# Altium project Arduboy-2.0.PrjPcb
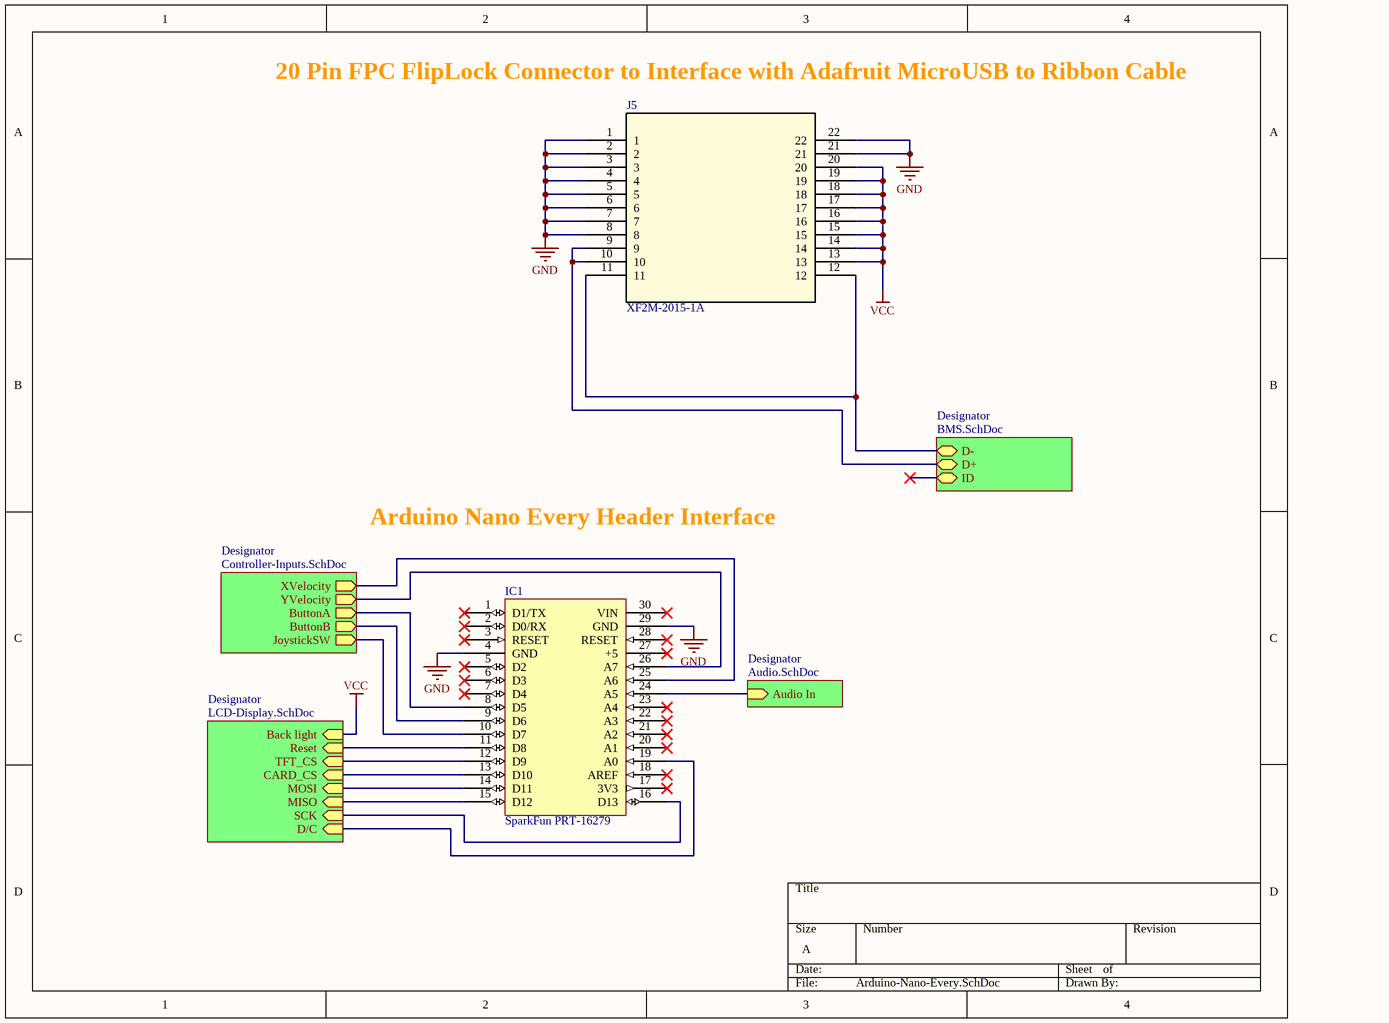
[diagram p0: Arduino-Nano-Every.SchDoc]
5 sheets, 40 parts. Net scope: hierarchical (ports join the sheet entries above them; power ports are global).
Sheets:
  Arduino-Nano-Every.SchDoc
    Designator = BMS.SchDoc
    Designator = Controller-Inputs.SchDoc
    Designator = LCD-Display.SchDoc
    Designator = Audio.SchDoc

## Sheet Arduino-Nano-Every.SchDoc
size A; SheetNumber: 1; SheetTotal: 5

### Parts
IC1  SparkFun PRT-16279  [PCB-djo2kohhk2l0t1bx5udn-1]
J5  XF2M-2015-1A  [CON20_1X20_DRB_XF2C_TYC]

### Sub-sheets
Designator = BMS.SchDoc: ID (bidir), D- (bidir), D+ (bidir)
Designator = Controller-Inputs.SchDoc: XVelocity (out), ButtonA (out), YVelocity (out), JoystickSW (out), ButtonB (out)
Designator = LCD-Display.SchDoc: Back light (in), CARD_CS (in), D/C (in), MISO (in), MOSI (in), SCK (in), TFT_CS (in), Reset (in)
Designator = Audio.SchDoc: Audio In (in)

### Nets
GND: IC1.4(GND) IC1.29(GND) J5.1 J5.2 J5.3 J5.4 J5.5 J5.6 J5.7 J5.8 J5.21 J5.22
VCC: J5.13 J5.14 J5.15 J5.16 J5.17 J5.18 J5.19 J5.20 ; sheet Designator/Back light
NetC8_2: IC1.24(A5) ; sheet Designator/Audio In
NetIC1_8: IC1.8(D5) ; sheet Designator/ButtonA
NetIC1_9: IC1.9(D6) ; sheet Designator/ButtonB
NetIC1_10: IC1.10(D7) ; sheet Designator/JoystickSW
NetIC1_11: IC1.11(D8) ; sheet Designator/Reset
NetIC1_12: IC1.12(D9) ; sheet Designator/TFT_CS
NetIC1_13: IC1.13(D10) ; sheet Designator/CARD_CS
NetIC1_14: IC1.14(D11) ; sheet Designator/MOSI
NetIC1_15: IC1.15(D12) ; sheet Designator/MISO
NetIC1_16: IC1.16(D13) ; sheet Designator/SCK
NetIC1_19: IC1.19(A0) ; sheet Designator/D/C
NetIC1_25: IC1.25(A6) ; sheet Designator/XVelocity
NetIC1_26: IC1.26(A7) ; sheet Designator/YVelocity
NetJ3_2: J5.11 J5.12 ; sheet Designator/D-
NetJ3_3: J5.9 J5.10 ; sheet Designator/D+

Not connected (* = marked no-connect by the designer): IC1 1(D1/TX)* 2(D0/RX)* 3(RESET)* 5(D2)* 6(D3)* 7(D4)* 17(3V3)* 18(AREF)* 20(A1)* 21(A2)* 22(A3)* 23(A4)* 27(+5)* 28(RESET)* 30(VIN)*

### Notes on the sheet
- 20 Pin FPC FlipLock Connector to Interface with Adafruit MicroUSB to Ribbon Cable
- Arduino Nano Every Header Interface

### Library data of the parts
IC1 = CMP-cc85030fd7841342-2: Arduino Nano Stackable Headers
J5 = XF2M-2015-1A: No Description Available; Mfr_Name: Omron

## Sheet BMS.SchDoc
size A; SheetNumber: 4; SheetTotal: 5
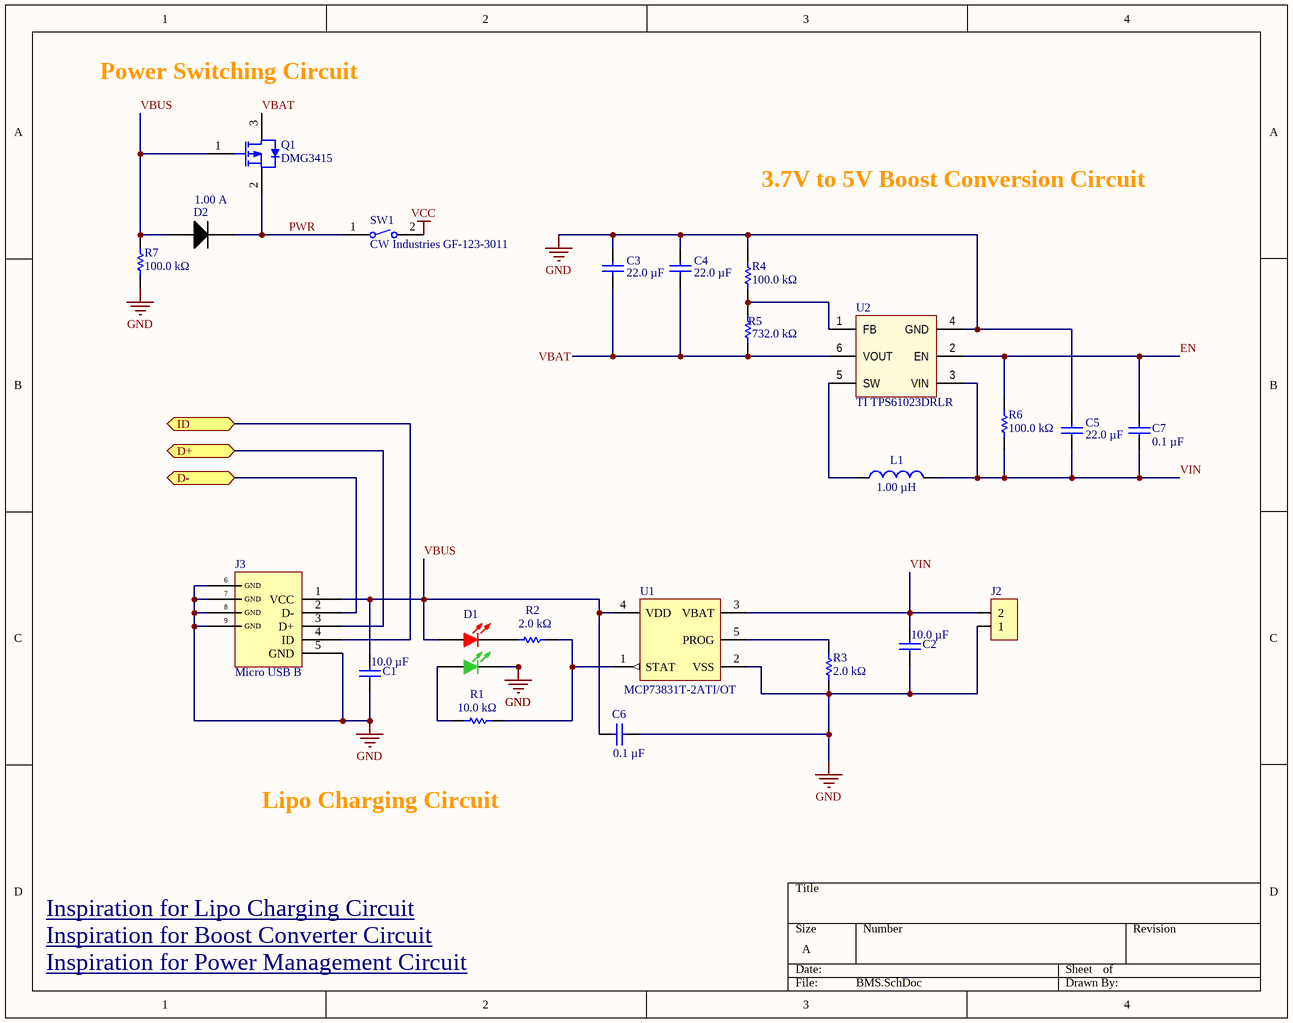
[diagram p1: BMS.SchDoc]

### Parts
C1  Capacitance: 10.0 µF  [CAPC2013X140X50LL20T25]  (hidden comment: Yageo CC0805ZKY5V6BB106)
C2  Capacitance: 10.0 µF  [CAPC2013X140X50LL20T25]  (hidden comment: Yageo CC0805ZKY5V6BB106)
C3  Capacitance: 22.0 µF  [0805_A]  (hidden comment: Murata GRM21BR60J226ME39L)
C4  Capacitance: 22.0 µF  [0805_A]  (hidden comment: Murata GRM21BR60J226ME39L)
C5  Capacitance: 22.0 µF  [0805_A]  (hidden comment: Murata GRM21BR60J226ME39L)
C6  Capacitance: 0.1 µF  [PCB-nrkqodghfh3vhkjrqn6s-1]  (hidden comment: Capacitor 0.1 uF 50V 0805 smd)
C7  Capacitance: 0.1 µF  [PCB-nrkqodghfh3vhkjrqn6s-1]  (hidden comment: Capacitor 0.1 uF 50V 0805 smd)
D1  Kingbright APHBM2012SURKCGKC  [PCB-7tltpeahe5b5uing7o0a-1]  (value not drawn)
D2  Current Rating: 1.00 A  [PCB-ug07xgv2o38opsue5tpb-1]  (hidden comment: ON Semiconductor MBR120VLSFT1G)
J2  JST S2B-PH-SM4-TB(LF)(SN)  [PCB-h6x3au1s0qq8morn82dx-1]  (value not drawn)
J3  Micro USB B  [PCB-c9crxyc84g0j6lvlvhpi-1]
L1  Inductance: 1.00 µH  [PCB-3ds7kv8g063ufwtygslx-1]  (hidden comment: Murata LQM21PN1R0MC0D)
Q1  DMG3415  [SOT-23-OT5_N]
R1  Resistance: 10.0 kΩ  [R0805-Medium]  (hidden comment: TE Connectivity CRGCQ0805J10K)
R2  Resistance: 2.0 kΩ  [RESC2013X55X40NL15T20]  (hidden comment: Vishay Dale TNPW08052K00BEEN)
R3  Resistance: 2.0 kΩ  [RESC2013X55X40NL15T20]  (hidden comment: Vishay Dale TNPW08052K00BEEN)
R4  Resistance: 100.0 kΩ  [RESC2013X70X40ML20T20]  (hidden comment: TE Connectivity CRG0805F100K)
R5  Resistance: 732.0 kΩ  [RESC2013X60X35ML10T20]  (hidden comment: Yageo RC0805FR-07732KL)
R6  Resistance: 100.0 kΩ  [RESC2013X70X40ML20T20]  (hidden comment: TE Connectivity CRG0805F100K)
R7  Resistance: 100.0 kΩ  [RESC2013X70X40ML20T20]  (hidden comment: TE Connectivity CRG0805F100K)
SW1  CW Industries GF-123-3011  [CW Industries GF-123-3011-Footprint-1]
U1  Manufacturer Part Number: MCP73831T-2ATI/OT  [PCB-hce6raeqrv828cqzeise-1]  (hidden comment: Microchip MCP73831T-2ATI/OT)
U2  TI TPS61023DRLR  [PCB-9gpqar69ve17efqet7gk-1]

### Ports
D+ (bidir), D- (bidir), ID (bidir)

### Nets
GND: C1.1 C2.1 C3.1 C4.1 C5.1 C6.2 D1.3(K) J2.1 J3.5(GND) J3.6(GND) J3.7(GND) J3.8(GND) J3.9(GND) R3.1 R4.2 R7.1 U1.2(VSS) U2.4(GND)
VCC: SW1.2
EN: C7.2 R6.2 U2.2(EN)
PWR: D2.2 Q1.2(S) SW1.1
VBAT: C3.2 C4.2 Q1.3(D) R5.1 U2.6(VOUT)
VBUS: C1.2 C6.1 D1.1(A) D2.1 J3.1(VCC) Q1.1(G) R7.2 U1.4(VDD)
VIN: C2.2 C5.2 C7.1 J2.2 L1.2 R6.1 U1.3(VBAT) U2.3(VIN)
NetD1_2: D1.2(K) R2.1
NetD1_4: D1.4(A) R1.1
NetJ3_2: J3.2(D-) ; port D-
NetJ3_3: J3.3(D+) ; port D+
NetJ3_4: J3.4(ID) ; port ID
NetL1_1: L1.1 U2.5(SW)
NetR1_2: R1.2 R2.2 U1.1(STAT)
NetR3_2: R3.2 U1.5(PROG)
NetR4_1: R4.1 R5.2 U2.1(FB)

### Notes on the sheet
- Power Switching Circuit
- 3.7V to 5V Boost Conversion Circuit
- Lipo Charging Circuit
- Inspiration for Lipo Charging Circuit <https://learn.adafruit.com/adafruit-microlipo-and-minilipo-battery-chargers/downloads>
- Inspiration for Boost Converter Circuit <https://easyeda.com/modules/Boost-Converter-3-7v-to-5v-TPS61023_2b84b7cdfcae42f996d13042b59b4481>
- Inspiration for Power Management Circuit <https://electronics.stackexchange.com/questions/409496/automatic-charging-and-power-switch-between-usb-and-lipo-battery>

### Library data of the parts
C1 C2 = CMP-d9da12546697061d-3: 0805 10 uF 10 V -20 / +80 % Tolerance Y5V SMT Multilayer Ceramic Capacitor; Capacitance Tolerance: +80/-20%; Lead-Free Status: Lead Free; Voltage Rating (DC): 10.0 V
C3-C5 = CMP-19299736-5: Multilayer Ceramic Capacitors MLCC Surface Mount 0805 22uF 6.3 Volts X5R 20%; Voltage Rating (DC): 6.30 V; Lead-Free Status: Lead Free; Case/Package (SI): 2012
C6 C7 = CMP-7c9db7331183a35a-3: 0805 0.1 uF 50V ±10% Tol. X7R Surface Mount Multilayer Ceramic Capacitor; Manufacturer Part Number: 0805B104K500CT; Voltage Rating (DC): 50.0 V; Lead-Free Status: Lead Free
D1 = CMP-bab573b2cef36572-4: LEDs SMD Chip 2x1.2mm Red Green 220/80 mcd Chip LED 0805 Series
D2 = CMP-816629-7: Diode; Schottky Barrier; Vr 20V; If 1A; Pkg SOD-123FL; Vf 0.34V; Tj +125degc; Cs 45A; Polarity: Standard; Voltage Rating (DC): 20.0 V; Forward Voltage: 340 mV; Output Current: 1.00 A (max); Lead-Free Status: Lead Free
J2 = CMP-642996-20: PH Series 2 Position 2 mm Pitch Surface Mount Side Entry Shrouded Header; Gender: Male; Insulation Resistance: 1.00 GΩ; Number of Contacts: 2; Current Rating: 2.00 A; Lead-Free Status: Lead Free; Voltage Rating (AC): 100 V; Pin Pitch: 2.00 mm
J3 = CMP-2328464-25: Micro-USB B Receptacle with Flange, Bottom Mount, Surface Mount, Lead-Free, 0473460001
L1 = CMP-8ac3434340965504-3: Surface Mount High Frequency Inductor, LQM21PN Series, 1 H, 20%, 0805 [2012 Metric], 90 MHz; Lead-Free Status: Lead Free; Case/Package (SI): 2012
Q1 = CMP-f98d303a86e3264a-3: P-Channel 20 V 39 mO Surface Mount Enhancement Mode Mosfet - SOT-23; Manufacturer Part Number: DMG3415U-7; Power Dissipation: 900 mW; Lead-Free Status: Lead Free
R1 = CMP-ae52623458ed7195-5: Res Thick Film 0805 10K Ohm 5% 0.125W(1/8W) ±100ppm/C Pad SMD Automotive T/R; Power Rating: 125 mW; Voltage Rating (DC): 150 V; Temperature Coefficient: -100 ppm/°C to 100 ppm/°C; Case/Package (SI): 2012
R2 R3 = CMP-1953871-2: RES SMD 2K OHM 0.1% 1/8W 0805; Case/Package (SI): 2012; Lead-Free Status: Lead Free; Power Rating: 0.125 W; Temperature Coefficient: 25.0 ppm/°C; Voltage Rating (DC): 150.0 V
R4 R6 R7 = CMP-440c8df333ec9bcb-3: Resistor; Thick Film; Res 100 Kilohms; Pwr-Rtg 0.125 W; Tol 1%; SMT; 0805
R5 = CMP-1854483-2: RES SMD 732K OHM 1% 1/8W 0805; Case/Package (SI): 2012; Lead-Free Status: Lead Free; Power Rating: 0.125 W; Voltage Rating (DC): 300.0 V
SW1 = CMP-3068f942c884efaf-2: Switch Slide ON OFF SPST Top Slide 3A 125VAC 125VDC 10000Cycles Solder Lug Panel Mount
U1 = CMP-961386-11: Linear Battery Charger Controller Li-Ion/Li-Pol 15mA to 500mA 4.2V 5-Pin SOT-23 T/R; Lead-Free Status: Lead Free; Input Voltage (DC): 3.75 V (min), 6.00 V (max); Supply Voltage (DC): 6.00 V (max)
U2 = CMP-979a58de2dfe485d-11: 3-A boost converter with 0.5-V ultra-low input voltage 6-SOT-5X3 -40 to 125

## Sheet Controller-Inputs.SchDoc
size A; SheetNumber: 3; SheetTotal: 4
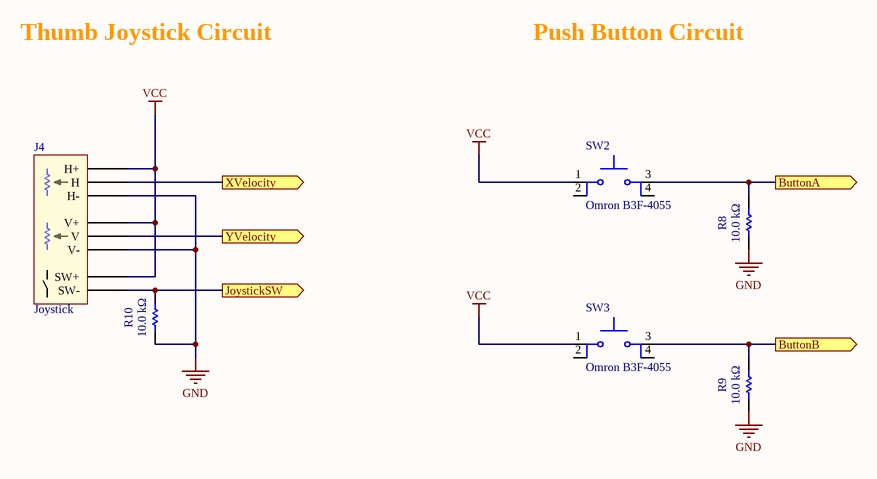
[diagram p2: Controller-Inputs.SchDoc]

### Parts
J4  Joystick  [PCB-lkedppk7goe399qnkd0w-1]
R8  Resistance: 10.0 kΩ  [R0805-Medium]  (hidden comment: TE Connectivity CRGCQ0805J10K)
R9  Resistance: 10.0 kΩ  [R0805-Medium]  (hidden comment: TE Connectivity CRGCQ0805J10K)
R10  Resistance: 10.0 kΩ  [R0805-Medium]  (hidden comment: TE Connectivity CRGCQ0805J10K)
SW2  Omron B3F-4055  [PCB-noalby8cjyi731n0he4x-1]
SW3  Omron B3F-4055  [PCB-noalby8cjyi731n0he4x-1]

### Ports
ButtonA (out), ButtonB (out), JoystickSW (out), XVelocity (out), YVelocity (out)

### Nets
GND: J4.H3(H-) J4.V3(V-) R8.1 R9.1 R10.1
VCC: J4.H1(H+) J4.SW1(SW+) J4.V1(V+) SW2.1 SW3.1
NetIC1_8: R8.2 SW2.3 ; port ButtonA
NetIC1_9: R9.2 SW3.3 ; port ButtonB
NetIC1_10: J4.SW2(SW-) R10.2 ; port JoystickSW
NetIC1_25: J4.H2(H) ; port XVelocity
NetIC1_26: J4.V2(V) ; port YVelocity

Not connected (* = marked no-connect by the designer): SW2 2 4; SW3 2 4

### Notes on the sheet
- Thumb Joystick Circuit
- Push Button Circuit

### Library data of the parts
J4 = CMP-d3091e8e8ab50cce-11: Thumb Joystick, 2-Axis Analog (10K Resistive) Output; Manufacturer Part Number: COM-09032
R8-R10 = CMP-ae52623458ed7195-5: as R1 on sheet BMS
SW2 SW3 = CMP-00f8c9f270e7df3f-1: Switch Tactile N.O. SPST Projected Plunger PC Pins 0.05A 24VDC 2.55N Thru-Hole Bag; Contact Resistance: 100 mΩ (max); Lead-Free Status: Lead Free; Contacts Type: SPST-NO; Contact Current Rating: 50.0 mA

## Sheet LCD-Display.SchDoc
size A; SheetNumber: 2; SheetTotal: 5
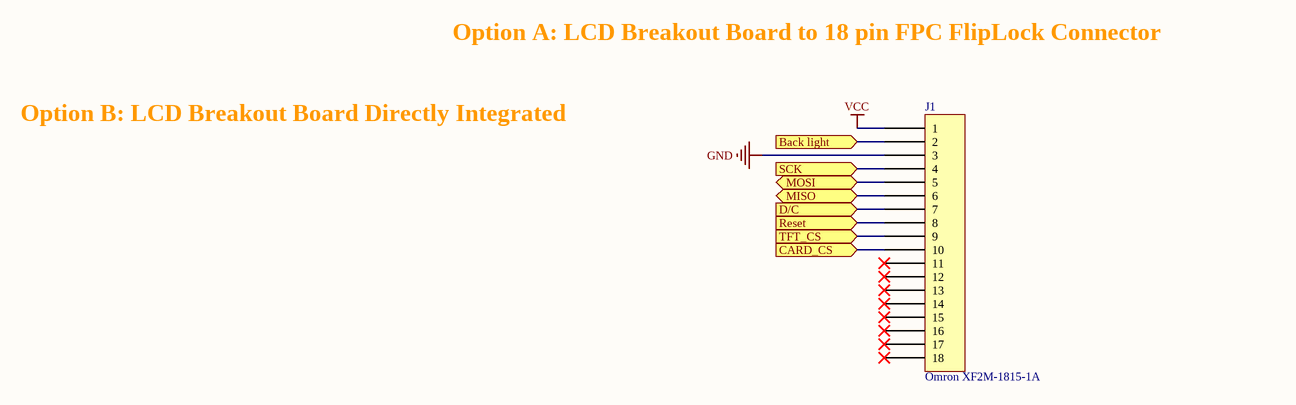
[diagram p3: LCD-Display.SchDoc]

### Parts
J1  Omron XF2M-1815-1A  [Omron XF2M-1815-1A-Footprint-1]

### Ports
Back light (in), CARD_CS (in), D/C (in), MISO (bidir), MOSI (bidir), Reset (in), SCK (in), TFT_CS (in)

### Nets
GND: J1.3
VCC: J1.1 J1.2 ; port Back light
NetIC1_11: J1.8 ; port Reset
NetIC1_12: J1.9 ; port TFT_CS
NetIC1_13: J1.10 ; port CARD_CS
NetIC1_14: J1.5 ; port MOSI
NetIC1_15: J1.6 ; port MISO
NetIC1_16: J1.4 ; port SCK
NetIC1_19: J1.7 ; port D/C

Not connected (* = marked no-connect by the designer): J1 11* 12* 13* 14* 15* 16* 17* 18*

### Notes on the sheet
- Option A: LCD Breakout Board to 18 pin FPC FlipLock Connector
- Option B: LCD Breakout Board Directly Integrated

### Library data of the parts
J1 = CMP-5d9a9493d482825d-4: FFC & FPC Connectors .5mm Rotary BackLock SMT Dual 18P Adhesv.; Pin Pitch: 500 µm; Current Rating: 500 mA; Number of Contacts: 18; Lead-Free Status: Lead Free; Gender: Female

## Sheet Audio.SchDoc
size A; SheetNumber: 5; SheetTotal: 5
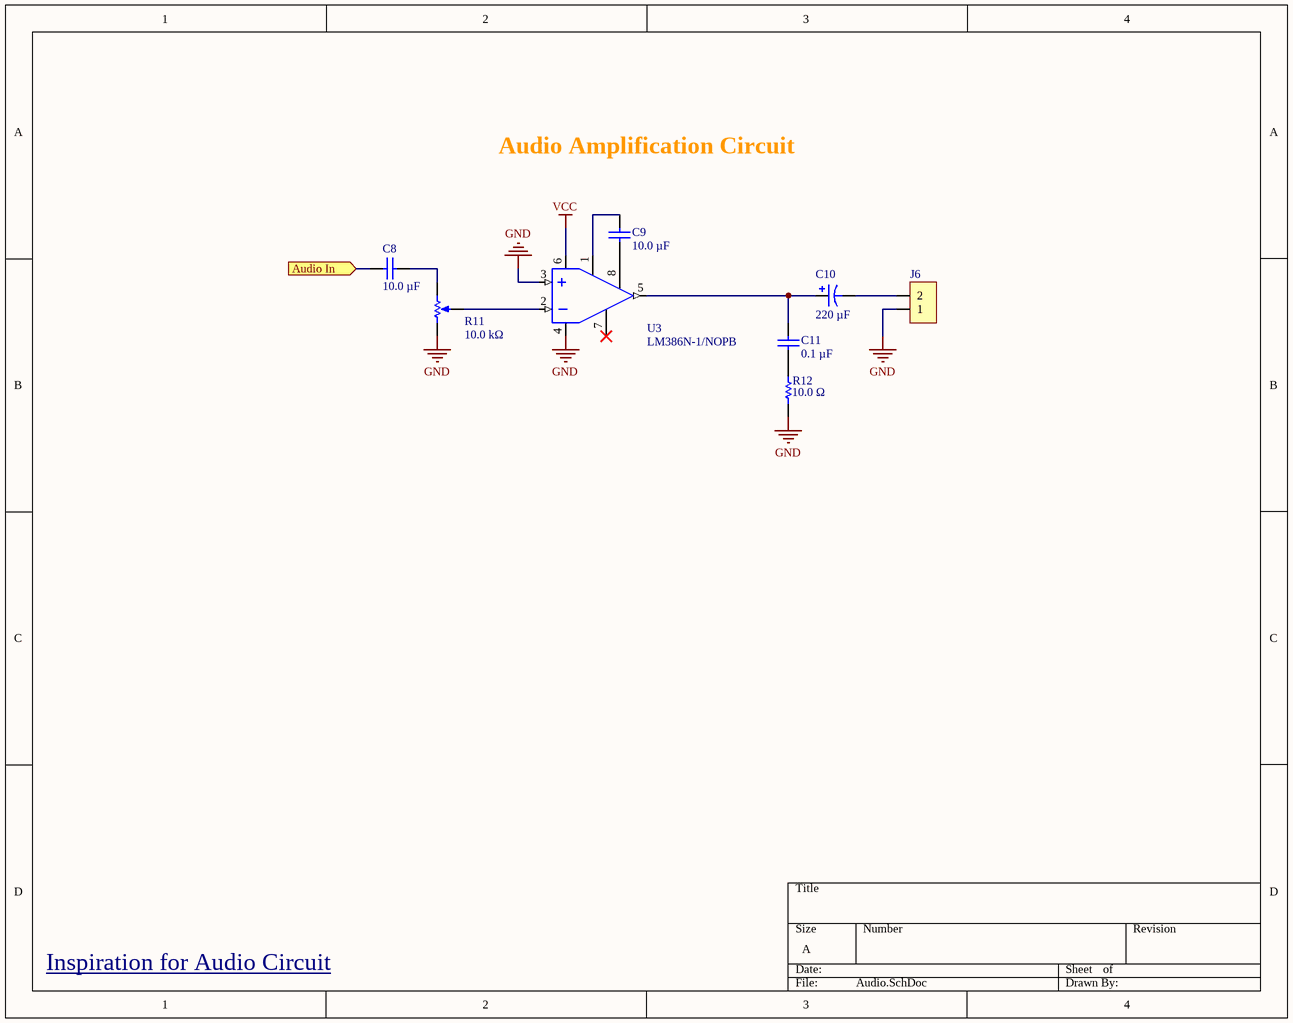
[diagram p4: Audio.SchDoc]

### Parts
C8  Capacitance: 10.0 µF  [CAPC2013X140X50LL20T25]  (hidden comment: Yageo CC0805ZKY5V6BB106)
C9  Capacitance: 10.0 µF  [CAPC2013X140X50LL20T25]  (hidden comment: Yageo CC0805ZKY5V6BB106)
C10  Capacitance: 220 µF  [PCB-82pg091iymoadsqs4g0s-1]  (hidden comment: Rubycon 50ZLH220MEFC10X16)
C11  Capacitance: 0.1 µF  [PCB-nrkqodghfh3vhkjrqn6s-1]  (hidden comment: Capacitor 0.1 uF 50V 0805 smd)
J6  JST S2B-PH-SM4-TB(LF)(SN)  [PCB-h6x3au1s0qq8morn82dx-1]  (value not drawn)
R11  Resistance: 10.0 kΩ  [PCB-ggf275ox9b8r0ysryhgv-1]  (hidden comment: Bourns 3352W-1-103LF)
R12  Resistance: 10.0 Ω  [Yageo RT0805BRD071RL-Footprint-1]  (hidden comment: Yageo AC0805FR-0710RL)
U3  LM386N-1/NOPB  [TI-P8]

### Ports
Audio In (in)

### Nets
GND: J6.1 R11.1(CCW) R12.1 U3.3(IN+) U3.4(GND)
VCC: U3.6(VS)
NetC8_1: C8.1 R11.3(CW)
NetC8_2: C8.2 ; port Audio In
NetC9_1: C9.1 U3.1(GAIN)
NetC9_2: C9.2 U3.8(GAIN)
NetC10_1: C10.1 C11.2 U3.5(VOUT)
NetC10_2: C10.2 J6.2
NetC11_1: C11.1 R12.2
NetR11_2: R11.2(WIPER) U3.2(IN-)

Not connected (* = marked no-connect by the designer): U3 7(BYPASS)*

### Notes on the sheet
- Audio Amplification Circuit
- Inspiration for Audio Circuit <https://docs.arduino.cc/tutorials/generic/simple-audio-player>

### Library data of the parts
C8 C9 = CMP-d9da12546697061d-3: as C1 on sheet BMS
C10 = CMP-3a26f21c550fe5e1-4: Cap Aluminum Lytic 220uF 50V 20% (10 X 16mm) Radial 5mm 1370mA 10000h 105°C Bulk; Dielectric Material: Aluminum Electrolytic; Voltage Rating (DC): 50.0 V
C11 = CMP-7c9db7331183a35a-3: as C6 on sheet BMS
J6 = CMP-642996-20: as J2 on sheet BMS
R11 = CMP-573f9e373add88f8-1: Res Cermet Trimmer 10K Ohm 20% 0.5W 1(Elec)/1(Mech)Turn (8.89 X 5.33 X 9.53mm) Pin Thru-Hole Bag; Power Rating: 500 mW; Lead-Free Status: Lead Free
R12 = CMP-7834257-3: Thick Film Resistors - SMD 1/8W 10ohm 1%; Lead-Free Status: Lead Free
U3 = CMP-1212651-4: Low Voltage Audio Power Amplifier, 0 to 70 degC, 8-pin DIP (P8), Green (RoHS & no Sb/Br); Gain: 20.0 dB; Number of Channels: 1; Supply Voltage (DC): 6.0 V; Quiescent Current: 0.004 A; Output Power: 0.325 W; Lead-Free Status: Contains Lead; Bandwidth: 300000.0 Hz

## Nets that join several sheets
GND: Arduino-Nano-Every (12 pins), BMS (18 pins), Controller-Inputs (5 pins), LCD-Display (J1.3), Audio (5 pins)
VCC: Arduino-Nano-Every (8 pins), BMS (SW1.2), Controller-Inputs (5 pins), LCD-Display (J1.1 J1.2), Audio (U3.6)
NetC8_2: Arduino-Nano-Every (IC1.24), Audio (C8.2)
NetIC1_8: Arduino-Nano-Every (IC1.8), Controller-Inputs (R8.2 SW2.3)
NetIC1_9: Arduino-Nano-Every (IC1.9), Controller-Inputs (R9.2 SW3.3)
NetIC1_10: Arduino-Nano-Every (IC1.10), Controller-Inputs (J4.SW2 R10.2)
NetIC1_11: Arduino-Nano-Every (IC1.11), LCD-Display (J1.8)
NetIC1_12: Arduino-Nano-Every (IC1.12), LCD-Display (J1.9)
NetIC1_13: Arduino-Nano-Every (IC1.13), LCD-Display (J1.10)
NetIC1_14: Arduino-Nano-Every (IC1.14), LCD-Display (J1.5)
NetIC1_15: Arduino-Nano-Every (IC1.15), LCD-Display (J1.6)
NetIC1_16: Arduino-Nano-Every (IC1.16), LCD-Display (J1.4)
NetIC1_19: Arduino-Nano-Every (IC1.19), LCD-Display (J1.7)
NetIC1_25: Arduino-Nano-Every (IC1.25), Controller-Inputs (J4.H2)
NetIC1_26: Arduino-Nano-Every (IC1.26), Controller-Inputs (J4.V2)
NetJ3_2: Arduino-Nano-Every (J5.11 J5.12), BMS (J3.2)
NetJ3_3: Arduino-Nano-Every (J5.9 J5.10), BMS (J3.3)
